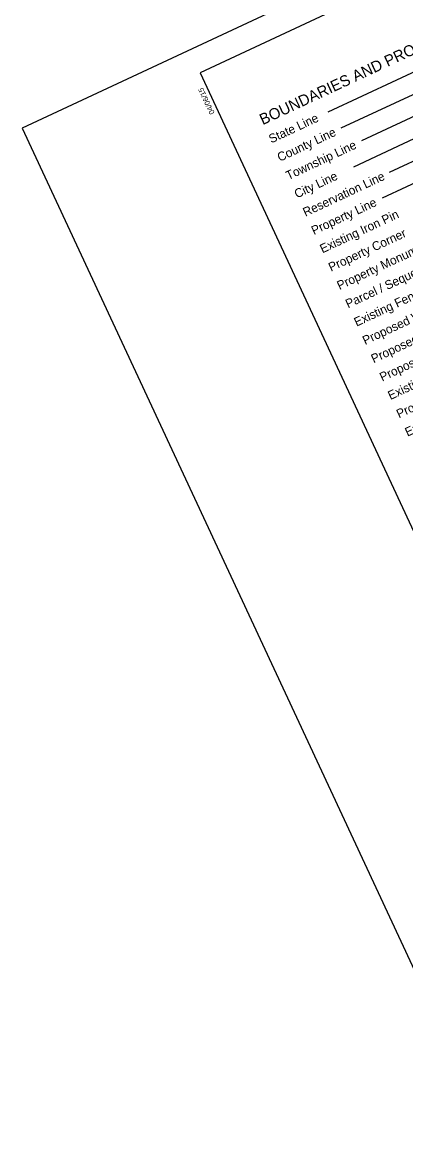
# Model space of a CAD drawing. Extents: x 885291.5 to 885341.7, y 651350.6 to 651393.5.
# Drawn here: x 885291.53 to 885301.03, y 651350.6 to 651378.14 of the extents above; entities that cross this region are included whole.
import ezdxf

# ---------------------------------------------------------------- set-up
doc = ezdxf.new("R2010")
doc.units = 0
for name, color, linetype in [('Sheet Summary Guardrail CELL', 7, 'Continuous'), ('Sheet Symbology CELL', 7, 'Continuous'), ('Stewart Plot Border Xerox6279 and LJ5000', 7, 'Continuous')]:
    doc.layers.add(name, color=color, linetype=linetype)

msp = doc.modelspace()

# ---------------------------------------------------------------- linework, layer by layer
at = {"layer": 'Sheet Symbology CELL'}
for p, q in [((885303.4, 651377.927), (885299.095, 651375.919)), ((885303.611, 651377.473), (885299.42, 651375.519)), ((885303.823, 651377.02), (885299.932, 651375.206)), ((885304.034, 651376.567), (885299.729, 651374.56)), ((885304.245, 651376.114), (885300.618, 651374.423)), ((885304.456, 651375.661), (885300.441, 651373.788))]:
    msp.add_line(p, q, dxfattribs=at)
msp.add_lwpolyline([(885329.923, 651392.736), (885295.937, 651376.888), (885307.02, 651353.12), (885341.006, 651368.969)], close=True, dxfattribs=at)
at = {"layer": 'Stewart Plot Border Xerox6279 and LJ5000'}
msp.add_lwpolyline([(885303.148, 651350.597), (885341.666, 651368.559), (885330.044, 651393.482), (885291.526, 651375.521)], close=True, dxfattribs=at)

# ---------------------------------------------------------------- texts
at = {"layer": 'Sheet Summary Guardrail CELL'}
msp.add_text('04/06/15', height=0.1313, rotation=115, dxfattribs=at).set_placement((885296.297, 651375.899))
at = {"layer": 'Sheet Symbology CELL'}
for s, height, p in [('BOUNDARIES AND PROPERTY:', 0.275, (885297.484, 651375.594)), ('State Line', 0.2188, (885297.696, 651375.142)), ('County Line', 0.21875, (885297.907, 651374.688)), ('Township Line', 0.21875, (885298.118, 651374.235)), ('City Line', 0.2188, (885298.33, 651373.782)), ('Reservation Line', 0.21875, (885298.541, 651373.329)), ('Property Line', 0.21875, (885298.752, 651372.876)), ('Existing Iron Pin', 0.21875, (885298.963, 651372.423)), ('Property Corner', 0.21875, (885299.175, 651371.969)), ('Property Monument', 0.21875, (885299.386, 651371.516)), ('Parcel / Sequence Number', 0.21875, (885299.597, 651371.063)), ('Existing Fence Line', 0.21875, (885299.809, 651370.61)), ('Proposed Woven Wire Fence', 0.21875, (885300.02, 651370.157)), ('Proposed Chain Link Fence', 0.21875, (885300.231, 651369.704)), ('Proposed Barbed Wire Fence', 0.21875, (885300.443, 651369.251)), ('Existing Wetland Boundary', 0.21875, (885300.647, 651368.794)), ('Existing Endangered Animal Boundary', 0.21875, (885301.07, 651367.888)), ('Proposed Wetland Boundary', 0.21875, (885300.859, 651368.341))]:
    msp.add_text(s, height=height, rotation=25, dxfattribs=at).set_placement(p)

doc.saveas('drawing.dxf')
